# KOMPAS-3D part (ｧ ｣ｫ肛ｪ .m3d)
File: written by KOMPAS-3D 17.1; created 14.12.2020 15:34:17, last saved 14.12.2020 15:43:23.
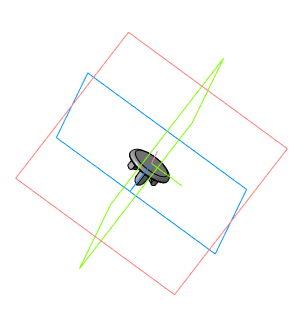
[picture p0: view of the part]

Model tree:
1. Эскиз:1
2. Элемент выдавливания:1
     Расстояние 1 = 1.2
3. Эскиз:2
4. Элемент выдавливания:2
     Расстояние 1 = 4
5. Эскиз:3
6. Элемент выдавливания:3
     Расстояние 2 = 4
7. Скругление:1
     Радиус = 1
8. Скругление:2
     Радиус = 1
